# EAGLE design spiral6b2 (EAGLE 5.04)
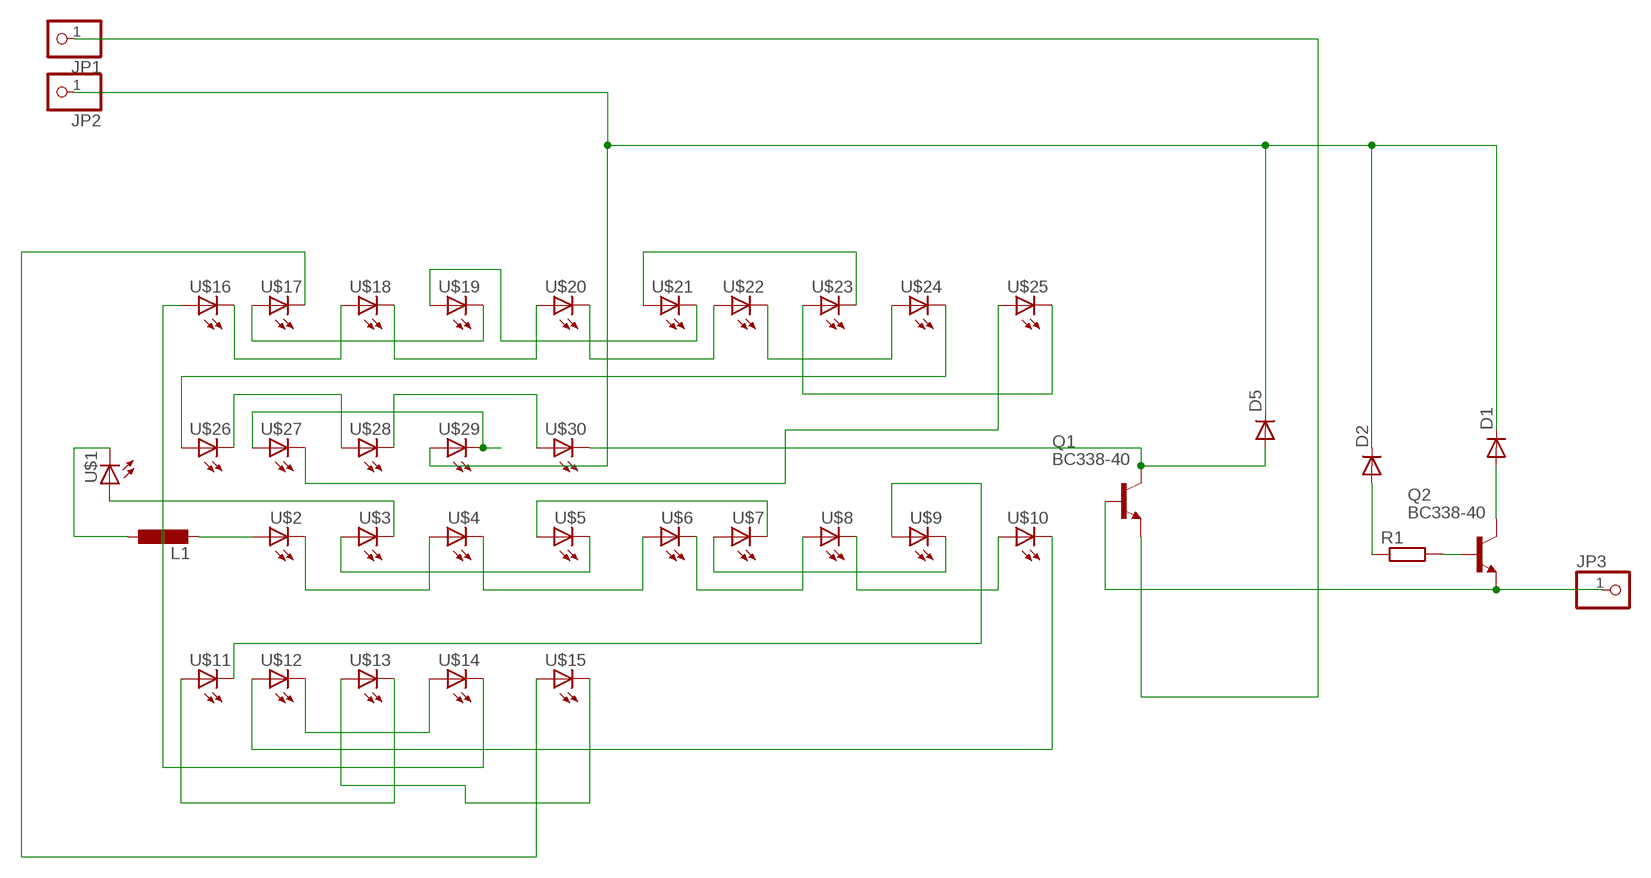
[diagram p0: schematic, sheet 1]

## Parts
D1  DIODE-D-2.5  [D-2.5]
D2  DIODE-D-2.5  [D-2.5]
D5  DIODE-D-2.5  [D-2.5]
JP1  PINHD-1X1  [1X01]
JP2  PINHD-1X1  [1X01]
JP3  PINHD-1X1  [1X01]
L1  L-EU0207/10  [0207/10]
Q1  BC338-40  [TO92-EBC]
Q2  BC338-40  [TO92-EBC]
R1  R-EU_0204/2V  [0204V]
U$1  LED5MM  [LED5MM]
U$2  LED5MM  [LED5MM]
U$3  LED5MM  [LED5MM]
U$4  LED5MM  [LED5MM]
U$5  LED5MM  [LED5MM]
U$6  LED5MM  [LED5MM]
U$7  LED5MM  [LED5MM]
U$8  LED5MM  [LED5MM]
U$9  LED5MM  [LED5MM]
U$10  LED5MM  [LED5MM]
U$11  LED5MM  [LED5MM]
U$12  LED5MM  [LED5MM]
U$13  LED5MM  [LED5MM]
U$14  LED5MM  [LED5MM]
U$15  LED5MM  [LED5MM]
U$16  LED5MM  [LED5MM]
U$17  LED5MM  [LED5MM]
U$18  LED5MM  [LED5MM]
U$19  LED5MM  [LED5MM]
U$20  LED5MM  [LED5MM]
U$21  LED5MM  [LED5MM]
U$22  LED5MM  [LED5MM]
U$23  LED5MM  [LED5MM]
U$24  LED5MM  [LED5MM]
U$25  LED5MM  [LED5MM]
U$26  LED5MM  [LED5MM]
U$27  LED5MM  [LED5MM]
U$28  LED5MM  [LED5MM]
U$29  LED5MM  [LED5MM]
U$30  LED5MM  [LED5MM]

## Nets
N$1: JP1.1 Q1.E
N$2: U$2.K(C) U$4.A
N$3: U$4.K(C) U$6.A
N$4: U$6.K(C) U$8.A
N$5: U$8.K(C) U$10.A
N$6: U$1.A U$3.K(C)
N$7: U$3.A U$5.K(C)
N$8: U$5.A U$7.K(C)
N$9: U$7.A U$9.K(C)
N$10: U$10.K(C) U$12.A
N$11: U$12.K(C) U$14.A
N$12: U$14.K(C) U$16.A
N$13: U$16.K(C) U$18.A
N$14: U$18.K(C) U$20.A
N$15: U$20.K(C) U$22.A
N$16: U$22.K(C) U$24.A
N$17: U$24.K(C) U$26.A
N$18: U$26.K(C) U$28.A
N$19: U$28.K(C) U$30.A
N$20: D2.A R1.1
N$21: L1.2 U$2.A
N$22: L1.1 U$1.K(C)
N$23: U$27.A U$29.K(C)
N$24: U$25.A U$27.K(C)
N$25: Q2.B R1.2
N$26: D1.A Q2.C
N$27: U$9.A U$11.K(C)
N$29: U$11.A U$13.K(C)
N$30: U$13.A U$15.K(C)
N$31: U$15.A U$17.K(C)
N$32: U$17.A U$19.K(C)
N$33: U$19.A U$21.K(C)
N$34: U$21.A U$23.K(C)
N$35: U$23.A U$25.K(C)
N$36: D5.A Q1.C U$30.K(C)
N$40: JP3.1 Q1.B Q2.E
V300: D1.C D2.C D5.C JP2.1 U$29.A

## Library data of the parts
D1 D2 D5 = diode-1:DIODE-: DIODE
JP1-JP3 = pinhead:PINHD-1X1: PIN HEADER
L1 = rcl-2:L-EU: INDUCTOR, European symbol
Q1 Q2 = transistor-npn:BC338*: NPN Transistor
R1 = rcl-2:R-EU_: RESISTOR, European symbol
U$1-U$30 = led(2):LED: LED

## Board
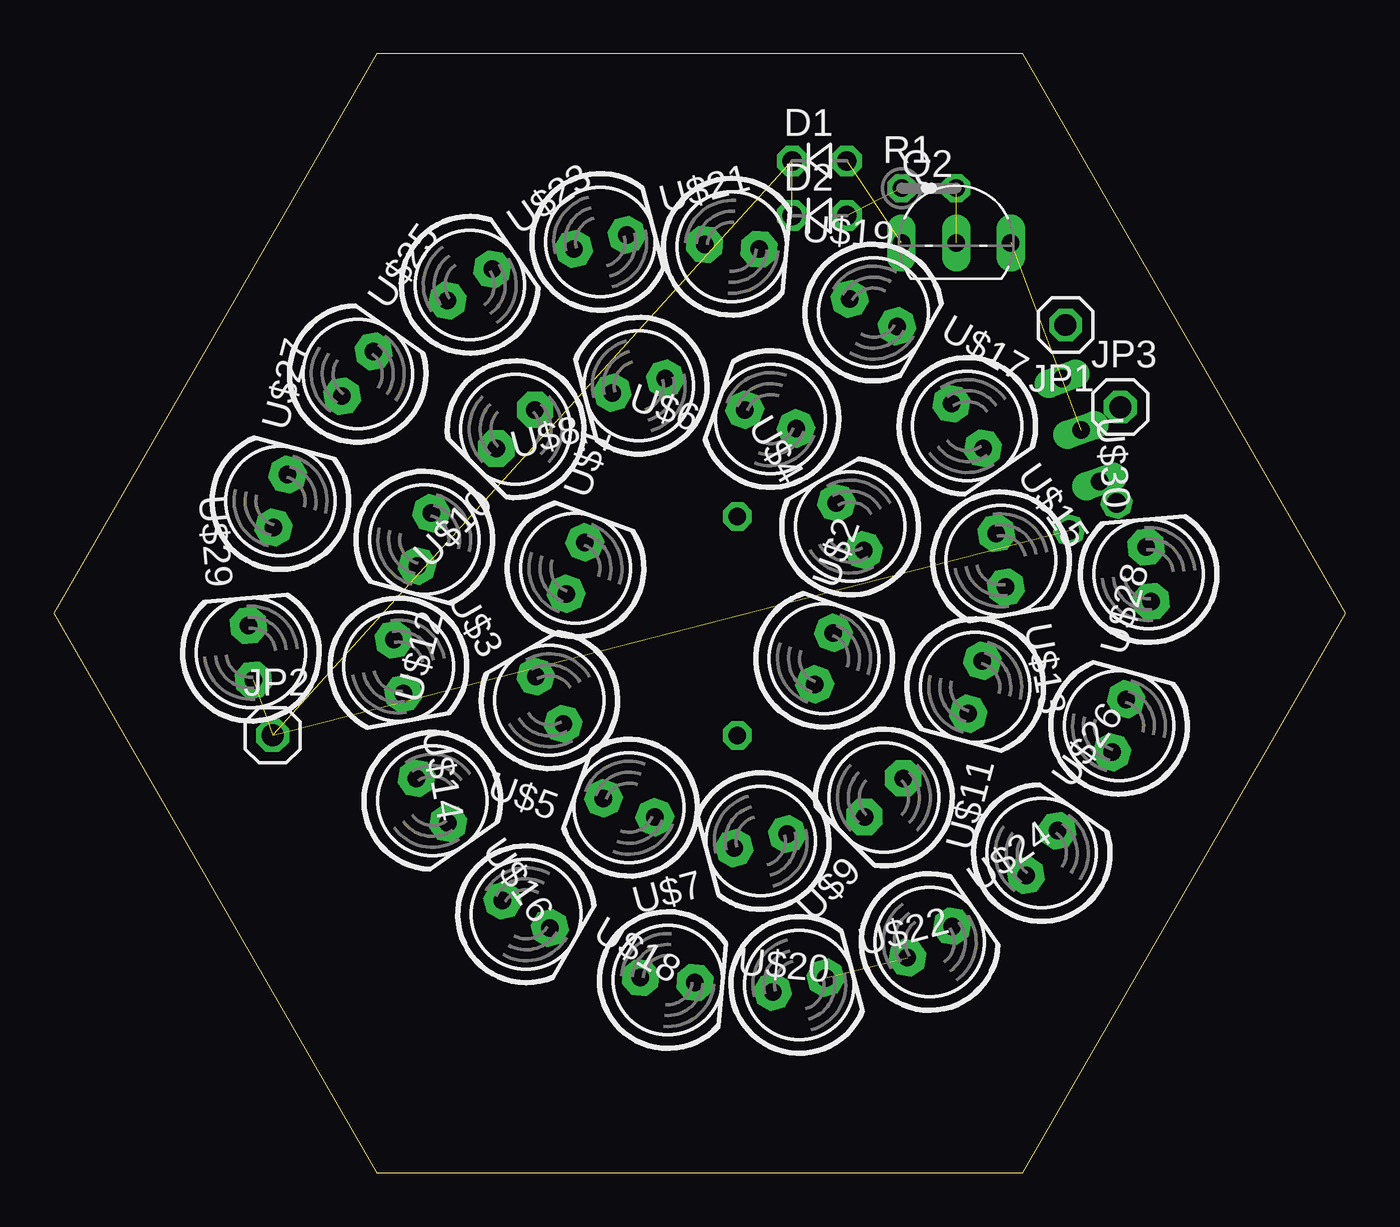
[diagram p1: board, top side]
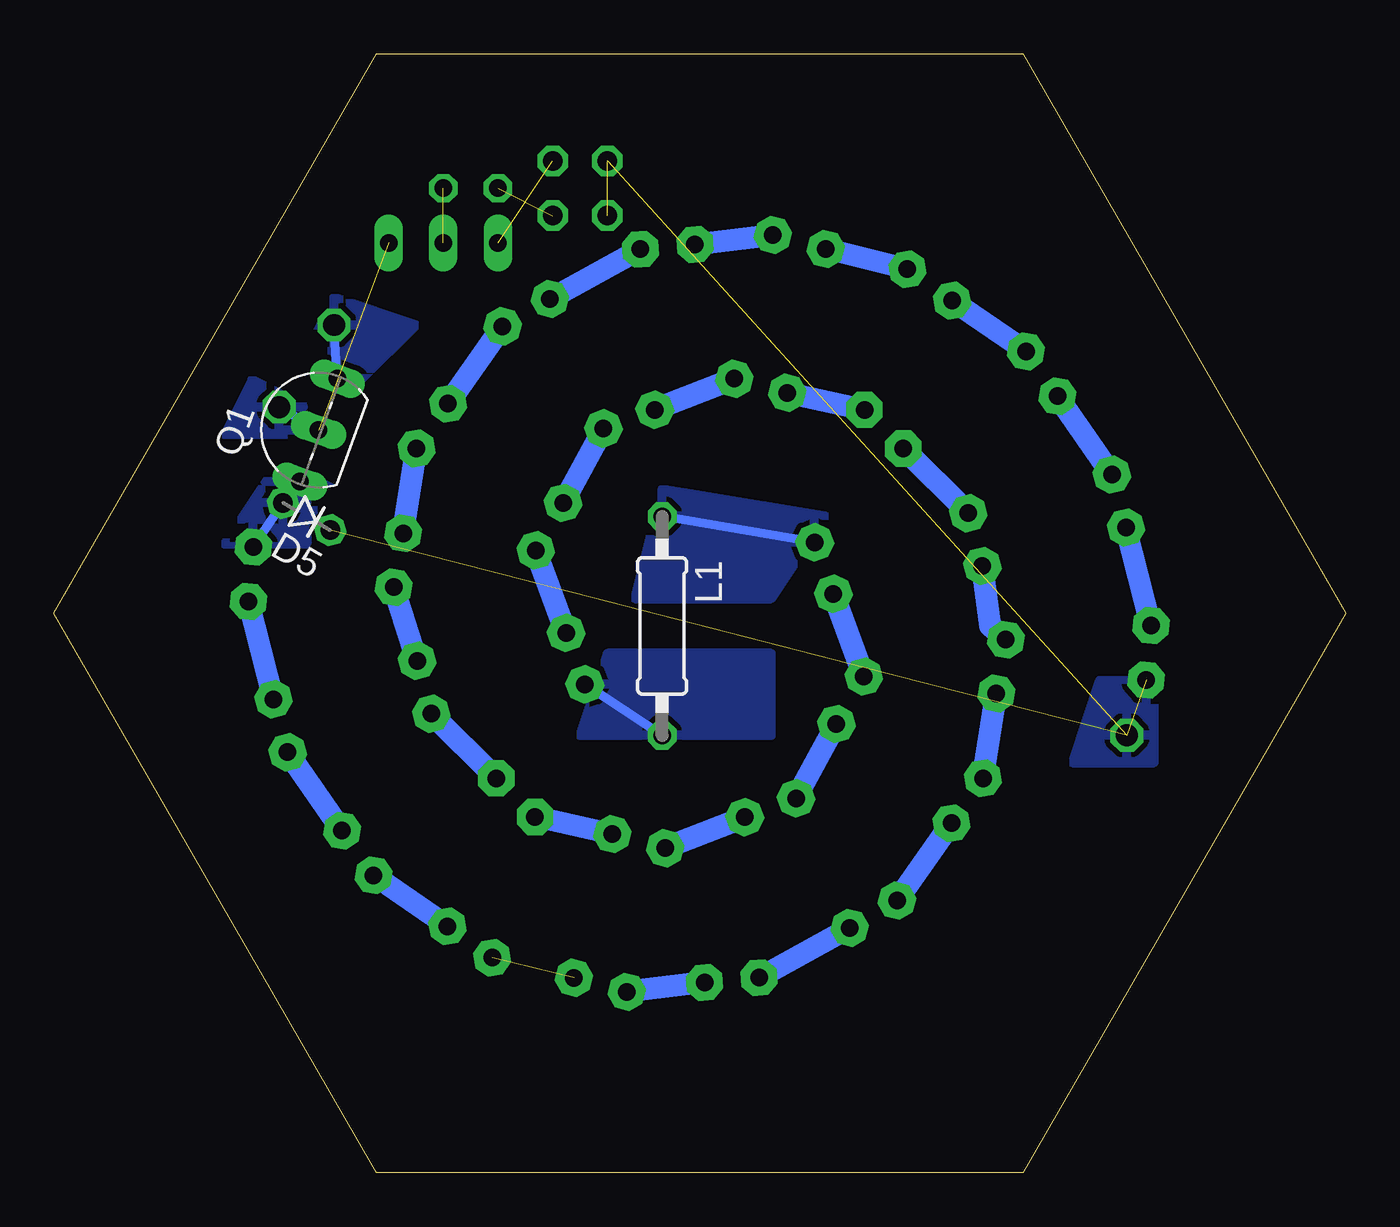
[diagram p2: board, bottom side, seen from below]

Size 60 x 51.96 mm. Coordinates in mm from the lower left corner, seen from the top.
Outline: 15,0 45,0 60,25.98 45,51.96 15,51.96 0,25.98 15,0
Copper layers (1*16): Top 0.035mm / dielectric 1.5mm / Bottom 0.035mm
Design rules "default": minimum track width 10mil, minimum drill 24mil, track to track 8mil, track to pad 8mil, pad to pad 8mil, via to via 8mil, smd to smd 8mil, copper to edge 40mil, drill to drill 8mil, minimum pad ring 10mil, minimum via ring 8mil, stop-mask expansion 4mil, vias tented up to drill 0mil, thermal gap 10mil

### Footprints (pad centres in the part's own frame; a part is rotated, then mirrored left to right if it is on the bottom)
D-2.5 = drill 0.9 octagon: A 1.27,0; C -1.27,0
1X01 = drill 1.016 octagon: 1 0,0
0207/10 = drill 0.813 octagon: 1 -5.08,0; 2 5.08,0
TO92-EBC = drill 0.813 long: B 0,-1.27; C -2.54,-1.27; E 2.54,-1.27
0204V = drill 0.813 octagon: 1 -1.27,0; 2 1.27,0
LED5MM = drill 0.813 pad 1.676 octagon: A -1.27,0; K 1.27,0

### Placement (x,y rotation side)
D1  35.56,46.99 0 top
D2  35.56,44.45 0 top
D5  48.26,30.48 150 bottom
JP1  46.99,39.37 180 top
JP2  10.16,20.32 0 top
JP3  49.53,35.56 0 top
L1  31.75,25.4 270 bottom
Q1  48.9,34.92 70 bottom
Q2  41.91,44.45 0 top
R1  40.64,45.72 0 top
U$1  24.23,28.08 70 top
U$2  35.77,23.88 70 top
U$3  23.02,21.95 120 top
U$4  36.98,30.01 120 top
U$5  26.72,16.96 160 top
U$6  33.28,35 160 top
U$7  32.83,15.41 195 top
U$8  27.17,36.55 195 top
U$9  38.55,17.43 225 top
U$10  21.45,34.53 225 top
U$11  42.8,22.55 255 top
U$12  17.2,29.41 255 top
U$13  43.99,28.45 280 top
U$14  16.01,23.51 280 top
U$15  42.42,34.68 305 top
U$16  17.58,17.28 305 top
U$17  38.06,39.95 330 top
U$18  21.94,12.01 330 top
U$19  31.49,43 355 top
U$20  28.51,8.96 355 top
U$21  25.38,43.23 14.9 top
U$22  34.62,8.73 14.9 top
U$23  19.32,41.23 35 top
U$24  40.68,10.73 35 top
U$25  14.12,37.1 54.9 top
U$26  45.88,14.86 54.9 top
U$27  10.53,31.2 75 top
U$28  49.47,20.76 75 top
U$29  9.15,24.16 95 top
U$30  50.85,27.8 95 top

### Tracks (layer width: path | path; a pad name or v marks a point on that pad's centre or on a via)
N$1
  Bottom 0.406: Q1.E JP1.1
  pour Bottom: 45.72,36.83 43.18,39.37 46.99,40.64 48.26,38.1 46.99,36.83
N$2
  Bottom 1.016: U$2.K U$4.A
N$3
  Bottom 1.016: U$6.A U$4.K
N$4
  Bottom 1.016: U$8.A U$6.K
N$5
  Bottom 1.016: U$10.A U$8.K
N$6
  Bottom 1.016: U$3.K U$1.A
N$7
  Bottom 1.016: U$5.K U$3.A
N$8
  Bottom 1.016: U$5.A U$7.K
N$9
  Bottom 1.016: U$7.A U$9.K
N$10
  Bottom 1.016: U$12.A U$10.K
N$11
  Bottom 1.016: U$12.K 16.51,25.4 U$14.A
N$12
  Bottom 1.016: U$16.A U$14.K
N$13
  Bottom 1.016: U$18.A U$16.K
N$14
  Bottom 1.016: U$20.A U$18.K
N$15
  Bottom 1.016: U$20.K U$22.A
N$16  (1 unrouted)
N$17
  Bottom 1.016: U$24.K U$26.A
N$18
  Bottom 1.016: U$26.K U$28.A
N$19
  Bottom 1.016: U$28.K U$30.A
N$20  (1 unrouted)
N$21
  Bottom 0.406: L1.2 U$2.A
  pour Bottom: 34.29,24.13 35.56,20.32 26.67,20.32 26.67,24.13
N$22
  Bottom 0.406: U$1.K L1.1
  pour Bottom: 24.13,30.48 31.75,31.75 33.02,26.67 26.67,26.67
N$23
  Bottom 1.016: U$29.K U$27.A
N$24
  Bottom 1.016: U$27.K U$25.A
N$25  (1 unrouted)
N$26  (1 unrouted)
N$27
  Bottom 1.016: U$9.A U$11.K
N$29
  Bottom 1.016: U$11.A U$13.K
N$30
  Bottom 1.016: U$13.A U$15.K
N$31
  Bottom 1.016: U$15.A U$17.K
N$32
  Bottom 1.016: U$19.K 36.83,40.64 U$17.A
N$33
  Bottom 1.016: U$19.A U$21.K
N$34
  Bottom 1.016: U$23.K U$21.A
N$35
  Bottom 1.016: U$25.K U$23.A
N$36
  Bottom 0.406: Q1.C D5.A U$30.K
  pour Bottom: 49.53,33.02 52.07,29.21 48.26,29.21 46.99,31.75
N$40  (1 unrouted)
  Bottom 0.406: Q1.B JP3.1
  pour Bottom: 48.26,35.56 50.8,36.83 52.07,34.29 48.26,34.29
V300  (4 unrouted)
  pour Bottom: 8.89,22.86 11.43,22.86 12.7,19.05 8.89,19.05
